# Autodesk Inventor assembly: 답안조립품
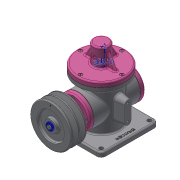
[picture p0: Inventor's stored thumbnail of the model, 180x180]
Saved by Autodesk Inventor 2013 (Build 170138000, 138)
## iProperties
Created: 2020-02
Part Number: 답안조립품
Document SubType Name: Assembly
Designer: Administrator
Author: Administrator
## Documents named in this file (21)
- C:\Users\Administrator\Desktop\600206V1011\600206V1011\답안조립품.iam
- C:\Users\Administrator\Desktop\600206V1011\600206V1011\본체.ipt
- C:\Users\Administrator\Desktop\600206V1011\600206V1011\E-링.ipt
- C:\Users\Administrator\Desktop\600206V1011\600206V1011\V-벨트풀리.ipt
- C:\Users\Administrator\Desktop\600206V1011\600206V1011\가변스프링.ipt
- C:\Users\Administrator\Desktop\600206V1011\600206V1011\개스킷 A.ipt
- C:\Users\Administrator\Desktop\600206V1011\600206V1011\개스킷 B.ipt
- C:\Users\Administrator\Desktop\600206V1011\600206V1011\덮개.ipt
- C:\Users\Administrator\Desktop\600206V1011\600206V1011\뒤커버.ipt
- C:\Users\Administrator\Desktop\600206V1011\600206V1011\링크.ipt
- C:\Users\Administrator\Desktop\600206V1011\600206V1011\베어링 17 x 40 x 12.ipt
- C:\Users\Administrator\Desktop\600206V1011\600206V1011\볼트 M4 x 10.ipt
- C:\Users\Administrator\Desktop\600206V1011\600206V1011\슬라이더.ipt
- C:\Users\Administrator\Desktop\600206V1011\600206V1011\앞커버.ipt
- C:\Users\Administrator\Desktop\600206V1011\600206V1011\오일 실 17 30 8.ipt
- C:\Users\Administrator\Desktop\600206V1011\600206V1011\와셔 4x16.ipt
- C:\Users\Administrator\Desktop\600206V1011\600206V1011\육각 소켓 머리 볼트 M4 x 10.ipt
- C:\Users\Administrator\Desktop\600206V1011\600206V1011\클레비스 핀 6 x 22.ipt
- 클레비스 핀 6 x 22.ipt
- C:\Users\Administrator\Desktop\600206V1011\600206V1011\키 4 x 4 x 25.ipt
- C:\Users\Administrator\Desktop\600206V1011\600206V1011\편심축.ipt
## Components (6 placed, 5 different names)
1. E-링:1
2. V-벨트풀리:1 — 각도:2
3. 개스킷 A:1
4. 개스킷 B:1
5. 개스킷 A:2
6. 가변스프링:1
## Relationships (1: Angle 1)
- 각도:2 [Angle]: V-벨트풀리:1
